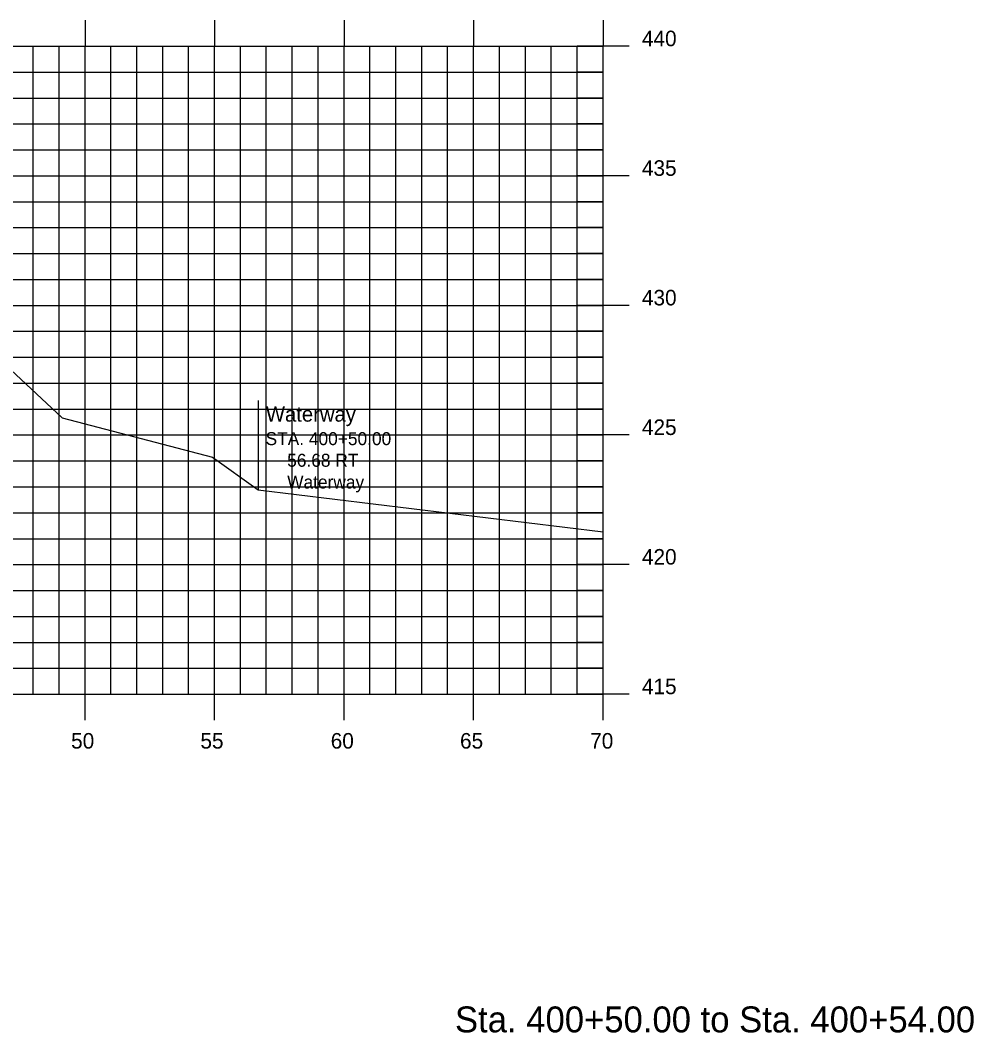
# Model space of a CAD drawing. Extents: x -161 to 764, y 111 to 210.
# Drawn here: x 201.67 to 238.48, y 114.11 to 153.17 of the extents above; entities that cross this region are included whole.
import ezdxf

# ---------------------------------------------------------------- set-up
doc = ezdxf.new("R2010")
doc.units = 0
for name, color, linetype in [('D_Text_Monospaced', 7, 'Continuous'), ('H_V ANNOTATION', 7, 'Continuous'), ('MAJOR', 7, 'Continuous'), ('MINOR', 7, 'Continuous'), ('S_Drainage_Waterway', 7, 'Continuous'), ('S_Roadway_Centerline', 7, 'Continuous')]:
    doc.layers.add(name, color=color, linetype=linetype)

msp = doc.modelspace()

# ---------------------------------------------------------------- linework, layer by layer
at = {"layer": 'MAJOR'}
for p, q in [((204.168, 153.171), (204.168, 152.169)), ((209.168, 153.171), (209.168, 152.169)), ((214.168, 153.171), (214.168, 152.169)), ((219.168, 153.171), (219.168, 152.169)), ((224.168, 153.171), (224.168, 152.169)), ((84.168, 152.169), (224.168, 152.169)), ((84.168, 152.169), (224.168, 152.169)), ((204.168, 127.169), (204.168, 152.169)), ((209.168, 127.169), (209.168, 152.169)), ((214.168, 127.169), (214.168, 152.169)), ((219.168, 127.169), (219.168, 152.169)), ((225.17, 152.169), (223.166, 152.169)), ((224.168, 127.169), (224.168, 152.169)), ((224.168, 127.169), (224.168, 152.169)), ((84.168, 147.169), (224.168, 147.169)), ((225.17, 147.169), (223.166, 147.169)), ((84.168, 142.169), (224.168, 142.169)), ((225.17, 142.169), (223.166, 142.169)), ((84.168, 137.169), (224.168, 137.169)), ((225.17, 137.169), (223.166, 137.169)), ((84.168, 132.169), (224.168, 132.169)), ((225.17, 132.169), (223.166, 132.169)), ((84.168, 127.169), (224.168, 127.169)), ((84.168, 127.169), (224.168, 127.169)), ((204.168, 126.167), (204.168, 127.169)), ((209.168, 126.167), (209.168, 127.169)), ((214.168, 126.167), (214.168, 127.169)), ((219.168, 126.167), (219.168, 127.169)), ((225.17, 127.169), (223.166, 127.169)), ((224.168, 126.167), (224.168, 127.169))]:
    msp.add_line(p, q, dxfattribs=at)
at = {"layer": 'MINOR'}
for p, q in [((202.168, 127.169), (202.168, 152.169)), ((203.168, 127.169), (203.168, 152.169)), ((205.168, 127.169), (205.168, 152.169)), ((206.168, 127.169), (206.168, 152.169)), ((207.168, 127.169), (207.168, 152.169)), ((208.168, 127.169), (208.168, 152.169)), ((210.168, 127.169), (210.168, 152.169)), ((211.168, 127.169), (211.168, 152.169)), ((212.168, 127.169), (212.168, 152.169)), ((213.168, 127.169), (213.168, 152.169)), ((215.168, 127.169), (215.168, 152.169)), ((216.168, 127.169), (216.168, 152.169)), ((217.168, 127.169), (217.168, 152.169)), ((218.168, 127.169), (218.168, 152.169)), ((220.168, 127.169), (220.168, 152.169)), ((221.168, 127.169), (221.168, 152.169)), ((222.168, 127.169), (222.168, 152.169)), ((223.168, 127.169), (223.168, 152.169)), ((84.168, 151.169), (224.168, 151.169)), ((224.168, 151.169), (223.166, 151.169)), ((84.168, 150.169), (224.168, 150.169)), ((224.168, 150.169), (223.166, 150.169)), ((84.168, 149.169), (224.168, 149.169)), ((224.168, 149.169), (223.166, 149.169)), ((84.168, 148.169), (224.168, 148.169)), ((224.168, 148.169), (223.166, 148.169)), ((84.168, 146.169), (224.168, 146.169)), ((224.168, 146.169), (223.166, 146.169)), ((84.168, 145.169), (224.168, 145.169)), ((224.168, 145.169), (223.166, 145.169)), ((84.168, 144.169), (224.168, 144.169)), ((224.168, 144.169), (223.166, 144.169)), ((84.168, 143.169), (224.168, 143.169)), ((224.168, 143.169), (223.166, 143.169)), ((84.168, 141.169), (224.168, 141.169)), ((224.168, 141.169), (223.166, 141.169)), ((84.168, 140.169), (224.168, 140.169)), ((224.168, 140.169), (223.166, 140.169)), ((84.168, 139.169), (224.168, 139.169)), ((224.168, 139.169), (223.166, 139.169)), ((84.168, 138.169), (224.168, 138.169)), ((224.168, 138.169), (223.166, 138.169)), ((84.168, 136.169), (224.168, 136.169)), ((224.168, 136.169), (223.166, 136.169)), ((84.168, 135.169), (224.168, 135.169)), ((224.168, 135.169), (223.166, 135.169)), ((84.168, 134.169), (224.168, 134.169)), ((224.168, 134.169), (223.166, 134.169)), ((84.168, 133.169), (224.168, 133.169)), ((224.168, 133.169), (223.166, 133.169)), ((84.168, 131.169), (224.168, 131.169)), ((224.168, 131.169), (223.166, 131.169)), ((84.168, 130.169), (224.168, 130.169)), ((224.168, 130.169), (223.166, 130.169)), ((84.168, 129.169), (224.168, 129.169)), ((224.168, 129.169), (223.166, 129.169)), ((84.168, 128.169), (224.168, 128.169)), ((224.168, 128.169), (223.166, 128.169))]:
    msp.add_line(p, q, dxfattribs=at)
at = {"layer": 'S_Drainage_Waterway'}
msp.add_line((210.852, 138.496), (210.852, 135.055), dxfattribs=at)
at = {"layer": 'S_Roadway_Centerline'}
msp.add_lwpolyline([(152.685, 140.854), (168.169, 142.293), (172.399, 142.133), (178.178, 142.122), (186.449, 141.953), (186.572, 141.953), (199.915, 140.445), (200.903, 140.058), (203.287, 137.833), (209.093, 136.316), (210.852, 135.055), (224.168, 133.439)], dxfattribs=at)

# ---------------------------------------------------------------- texts
at = {"layer": 'D_Text_Monospaced'}
for s, height, p in [('STA. 400+50.00', 0.49998, (211.139, 136.778)), ('56.68 RT ', 0.5, (211.973, 135.944)), ('Waterway', 0.5, (211.973, 135.104))]:
    msp.add_text(s, height=height, dxfattribs=at).set_placement(p)
at = {"layer": 'H_V ANNOTATION'}
for s, height, p in [('440', 0.6, (225.668, 152.169)), ('435', 0.6, (225.668, 147.169)), ('430', 0.6, (225.668, 142.169)), ('425', 0.6, (225.668, 137.169)), ('420', 0.6, (225.668, 132.169)), ('415', 0.6, (225.668, 127.169)), ('50', 0.6, (203.632, 125.069)), ('55', 0.6, (208.624, 125.069)), ('60', 0.6, (213.654, 125.069)), ('65', 0.6, (218.646, 125.069)), ('70', 0.6, (223.67, 125.069)), ('Sta. 400+50.00 to Sta. 400+54.00', 1.0002, (218.451, 114.12))]:
    msp.add_text(s, height=height, rotation=360, dxfattribs=at).set_placement(p)
at = {"layer": 'S_Drainage_Waterway'}
msp.add_text('Waterway', height=0.585, rotation=360, dxfattribs=at).set_placement((211.15, 137.684))

doc.saveas('drawing.dxf')
